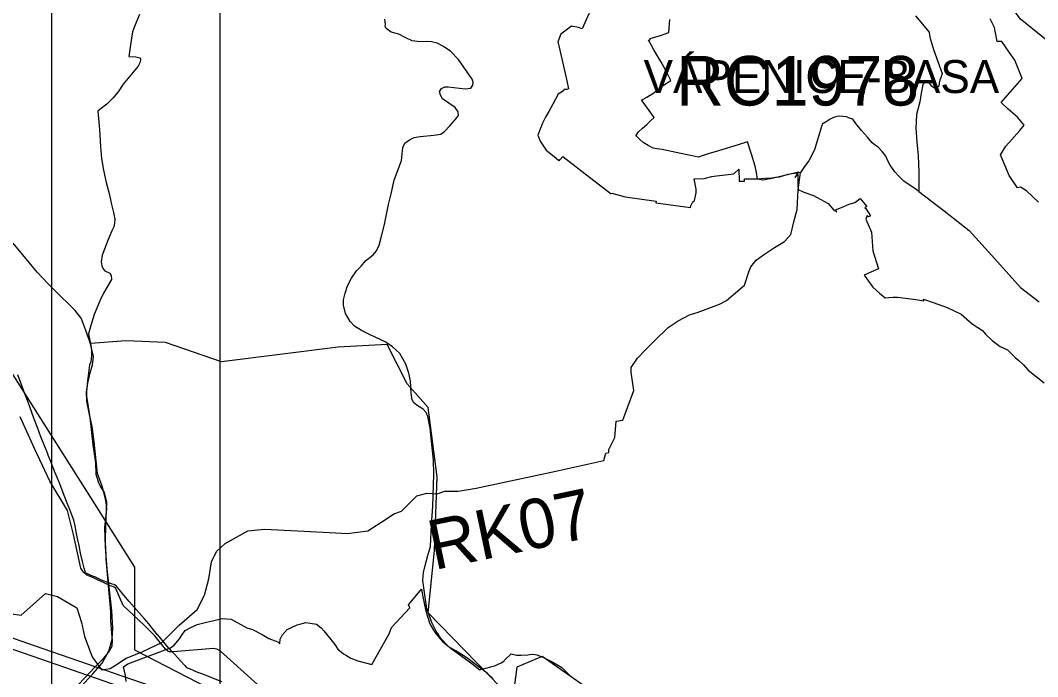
# Model space of a CAD drawing. Extents: x -789162 to -606354, y -1062736 to -945481.
# Drawn here: x -694982 to -691900, y -981501 to -979512 of the extents above; entities that cross this region are included whole.
import ezdxf

# ---------------------------------------------------------------- set-up
doc = ezdxf.new("R2010")
doc.units = 0
for name, color, linetype in [('_Rámeček', 7, 'Continuous'), ('_SIRSI VZTAHY_CYKLOTRASY MISTNI S', 7, 'Continuous'), ('_SIRSI VZTAHY_ELEKTRICKE VEDENI VN 110 kV S', 7, 'Continuous'), ('_SIRSI VZTAHY_ELEKTRICKE VEDENI VN 220 kV S', 7, 'Continuous'), ('_SIRSI VZTAHY_ELEKTRICKE VEDENI VN 400 kV N', 7, 'Continuous'), ('_SIRSI VZTAHY_NATURA_EVL', 7, 'Continuous'), ('_SIRSI VZTAHY_NATURA_EVL_POPIS_KOD', 7, 'Continuous'), ('_SIRSI VZTAHY_PRIRODNIHO PARKU', 7, 'Continuous'), ('_SIRSI VZTAHY_SILNICE III TRIDY_STAV', 7, 'Continuous'), ('_SIRSI VZTAHY_USES_NRBK_S', 7, 'Continuous'), ('_SIRSI VZTAHY_USES_popis S', 7, 'Continuous'), ('_SIRSI VZTAHY_USES_RBC_S', 7, 'Continuous'), ('_SIRSI VZTAHY_USES_RBK_S', 7, 'Continuous'), ('_SIRSI VZTAHY_VTL PLYNOVOD', 7, 'Continuous')]:
    doc.layers.add(name, color=color, linetype=linetype)

msp = doc.modelspace()

# ---------------------------------------------------------------- linework, layer by layer
at = {"layer": '_Rámeček'}
msp.add_lwpolyline([(-673887.2, -995977.3), (-673887.2, -966277.3), (-694887.2, -966277.3), (-694887.2, -995977.3)], close=True, dxfattribs=at)
msp.add_lwpolyline([(-674375.7, -995477.3), (-674375.7, -975976.1), (-694376.9, -975976.1), (-694376.9, -995477.3)], dxfattribs=at)
at = {"layer": '_SIRSI VZTAHY_CYKLOTRASY MISTNI S'}
for points in [[(-691816, -979617.5), (-691951.9, -979508.8), (-692110.7, -979287.6), (-692328, -979211), (-692523.8, -978708.8), (-692486.6, -978493.5), (-692726.7, -977966.7), (-692975.5, -977824), (-693210.7, -977775.4), (-693492.4, -977508.6), (-693619, -977388.9), (-693813.4, -977283.8), (-693821.4, -977198.8), (-693557.4, -977122)], [(-692561.9, -982005.8), (-692792.5, -981838.4), (-692978.4, -981716.2), (-693172.2, -981663), (-693275.7, -981527.5), (-693400.5, -981439.8), (-693477.5, -981471.7), (-693490.8, -981570), (-693745.7, -981307), (-693727.1, -981118.3), (-693719.2, -980895.1), (-693745.7, -980685.2), (-693809.4, -980613.5), (-693870.5, -980493.9), (-694019.2, -980501.9), (-694372.3, -980547.1), (-694542.3, -980488.6), (-694661.8, -980483.3), (-694768, -980491.3)]]:
    msp.add_lwpolyline(points, dxfattribs=at)
at = {"layer": '_SIRSI VZTAHY_ELEKTRICKE VEDENI VN 110 kV S'}
msp.add_lwpolyline([(-695099.9, -981351.1), (-694940.1, -981406.3), (-694671.1, -981499.1), (-694396.2, -981594), (-694167.4, -981672.8), (-693934.1, -981753.4), (-693724.7, -981825.6), (-693504, -981902.1), (-693347.5, -981908.6), (-693148.1, -981916.7), (-692888.5, -981927.1), (-692639.9, -981937.1), (-692439.7, -981945), (-692140.6, -981956.9), (-691924.8, -981965.3), (-691693.6, -981974.7)], dxfattribs=at)
at = {"layer": '_SIRSI VZTAHY_ELEKTRICKE VEDENI VN 220 kV S'}
msp.add_lwpolyline([(-698352.5, -980261.8), (-698011.7, -980379.6), (-697596.3, -980523), (-697419.8, -980584), (-697058, -980709.1), (-696683.3, -980838.6), (-696343.4, -980955.9), (-695974.2, -981083.5), (-695687.1, -981182.6), (-695361.5, -981294.9), (-695116.9, -981379.2), (-694705.9, -981521), (-694311.9, -981656.7), (-693963.7, -981776.7), (-693721.1, -981882.4), (-693400.8, -982021.6), (-693174.7, -982120.1), (-692744.9, -982307.1), (-692311.8, -982495.5), (-691885.3, -982681.2)], dxfattribs=at)
at = {"layer": '_SIRSI VZTAHY_ELEKTRICKE VEDENI VN 400 kV N'}
msp.add_lwpolyline([(-695022, -980558.7), (-694898.3, -980754), (-694781.6, -980938.6), (-694636.2, -981168.6), (-694635.8, -981419), (-694349.9, -981567.1), (-694229.6, -981729.7), (-693978.3, -981813.9), (-693730.2, -981922.8), (-693442.6, -982049), (-693232.3, -982141.5), (-692774.3, -982341.3), (-692334, -982533.2), (-692003.5, -982678), (-691832.7, -982796.8)], dxfattribs=at)
at = {"layer": '_SIRSI VZTAHY_NATURA_EVL'}
for points in [[(-693237.9, -979444), (-693279.9, -979537.8), (-693290.4, -979533.3), (-693311.8, -979529.6), (-693343.8, -979553.9), (-693353.5, -979577), (-693350.2, -979589.4), (-693340.9, -979628.3), (-693326.1, -979695.8), (-693321.5, -979719.4), (-693326, -979721.4), (-693329.1, -979721.3), (-693334.9, -979721.2), (-693336.4, -979725.2), (-693352.2, -979735.8), (-693368.7, -979766.3), (-693381.1, -979788.4), (-693389.5, -979803.6), (-693400.2, -979823.2), (-693414, -979860.1), (-693406.4, -979878.3), (-693388.9, -979905.6), (-693383.8, -979909.9), (-693364.9, -979925.1), (-693351.8, -979935.8), (-693349.4, -979937.9), (-693346.3, -979934), (-693338.1, -979924.8), (-693279.7, -979969.8), (-693191.9, -980037.4), (-693189.5, -980035.5), (-693149.2, -980047.2), (-693055.9, -980060.1), (-693056.4, -980065.1), (-692951.4, -980079.2), (-692950.4, -980074.1), (-692943.9, -980062.2), (-692939.4, -980057.7), (-692934.1, -980035.1), (-692934.7, -980024), (-692940.6, -979992.3), (-692910.4, -979991.1), (-692886.9, -979985.6), (-692872.2, -979983.6), (-692819.9, -979977.2), (-692804.7, -979963.3), (-692804.4, -979999.8), (-692787.8, -979999.8), (-692787.8, -979992.3), (-692749.2, -979991.9), (-692732.7, -979995.5), (-692725, -979994.1), (-692712, -979990.9), (-692707.7, -979990.9), (-692682.8, -979985.7), (-692623.8, -979970.6), (-692635.3, -979988.6), (-692626.2, -979978.8), (-692626.6, -979987.5), (-692626.4, -979999), (-692626.7, -980016.6), (-692625.2, -980020.8), (-692625, -980024.8), (-692607.6, -980033), (-692578.5, -980043.1), (-692534.2, -980067), (-692516.7, -980087.6), (-692511.3, -980090), (-692507.7, -980093.6), (-692512.1, -980085.9), (-692494.3, -980078.8), (-692471.1, -980069.2), (-692453.7, -980064.5), (-692437, -980051.5), (-692416.7, -980075.9), (-692422.9, -980079.8), (-692420.5, -980082.5), (-692406, -980104.3), (-692412, -980107.2), (-692416, -980103.5), (-692420.5, -980114.5), (-692403.1, -980153.6), (-692399.5, -980210.2), (-692382.2, -980264.9), (-692395.9, -980270.9), (-692425.2, -980283.7), (-692398.7, -980320.3), (-692379.2, -980339.1), (-692361.2, -980352.6), (-692350.3, -980352), (-692337.9, -980351.3), (-692324.3, -980350.9), (-692269.1, -980357.4), (-692244.9, -980361.9), (-692245.1, -980356.6), (-692215.9, -980367.2), (-692173.4, -980382.2), (-692130.9, -980402.1), (-692098.5, -980431.5), (-692067.1, -980451.9), (-692057.2, -980463.3), (-692037.7, -980482.4), (-692013.7, -980500.1), (-691991.2, -980510.4), (-691967.3, -980533.6), (-691957.1, -980543.2), (-691942.6, -980556.2), (-691928.1, -980572.4), (-691903.9, -980590.9), (-691880.3, -980609.9)], [(-691897.5, -980062.5), (-691933.1, -980028.5), (-691951.6, -980017.7), (-691960.9, -980019.2), (-691986.1, -979982.2), (-692012.2, -979919.1), (-691996.3, -979893.1), (-691953.5, -979846), (-691940.3, -979830), (-691960.5, -979805.2), (-691988.9, -979780.7), (-692010.5, -979760.8), (-691946.7, -979688.6), (-691969.3, -979632.6), (-691985.8, -979608.6), (-692008.6, -979576.5), (-692022.4, -979575.8), (-692027.7, -979549.6), (-692030.2, -979534.1), (-692043.8, -979507.1)]]:
    msp.add_lwpolyline(points, dxfattribs=at)
at = {"layer": '_SIRSI VZTAHY_PRIRODNIHO PARKU'}
for points in [[(-694621, -979494.7), (-694634, -979525.2), (-694642, -979547.3), (-694648, -979586.2), (-694653, -979621.4), (-694632, -979622.4), (-694620, -979625.2), (-694618, -979628.9), (-694619, -979638.8), (-694625, -979650.5), (-694670, -979705.8), (-694685, -979728.8), (-694702, -979748.1), (-694720, -979766.4), (-694741, -979782.4), (-694747, -979787.5), (-694742, -979842.4), (-694739, -979894.5), (-694736, -979930.6), (-694730, -979965.9), (-694722, -980003.4), (-694713, -980037.2), (-694706, -980070), (-694700, -980094.5), (-694695, -980114.6), (-694696, -980126.4), (-694699, -980137.3), (-694705, -980149.5), (-694718, -980181.4), (-694725, -980200.2), (-694734, -980223.8), (-694737, -980243.9), (-694735, -980255.7), (-694731, -980264.5), (-694726, -980271.4), (-694711, -980278.2), (-694707, -980284.9), (-694706, -980297.5), (-694730, -980338.6), (-694740, -980359.5), (-694758, -980403.2), (-694765, -980426.1), (-694770, -980443.9), (-694775, -980461.6), (-694769, -980492.3), (-694768, -980496.7), (-694766, -980513.6), (-694766, -980528.7), (-694768, -980546.7), (-694772, -980555.7), (-694778, -980604.6), (-694781, -980637), (-694781, -980643.5), (-694781, -980650.5), (-694771, -980715.3), (-694762, -980798), (-694754, -980853.2), (-694753, -980886.7), (-694749, -980899.5), (-694746, -980909.9), (-694739, -980925.2), (-694728, -980943), (-694724, -980958.6), (-694721, -980971.4), (-694722, -980999.6), (-694724, -981042), (-694725, -981089.8), (-694724, -981117.2), (-694723, -981126.7), (-694723, -981143.4), (-694716, -981225.2), (-694709, -981303.6), (-694709, -981320.7), (-694708.3, -981331.9), (-694706, -981368.5), (-694704, -981391.2), (-694705, -981408.9), (-694713, -981423.1), (-694734, -981449.2), (-694756, -981472), (-694805, -981523)], [(-694661, -981515.7), (-694663, -981497.4), (-694669, -981470.6), (-694656, -981462.1), (-694527, -981413.8), (-694516, -981404.8), (-694500, -981385.6), (-694490, -981372.2), (-694482, -981360.8), (-694465, -981352.2), (-694446, -981343.1), (-694418, -981335.5), (-694400, -981331.7), (-694370, -981324.3), (-694343, -981326.9), (-694296, -981353), (-694278, -981357.9), (-694249.4, -981372.8), (-694229.2, -981384.7), (-694202, -981395.1), (-694195.1, -981401.3), (-694195, -981386.9), (-694189, -981375.1), (-694173, -981358), (-694143, -981343.7), (-694135, -981341.6), (-694117, -981336.9), (-694084, -981342), (-694070, -981353), (-694062, -981361.4), (-694029, -981403.5), (-694020, -981416.9), (-694003, -981431.3), (-693994, -981436.5), (-693980, -981444.8), (-693959, -981452.7), (-693917, -981463.6), (-693864, -981371.3), (-693857, -981352.1), (-693802, -981292.4), (-693806, -981282.8), (-693766, -981235.3), (-693762, -981259), (-693754, -981296.7), (-693749, -981315.7), (-693741, -981340.8), (-693730, -981359.7), (-693724, -981369.3), (-693711, -981385.1), (-693702, -981394.9), (-693677, -981415.8), (-693614, -981460.4), (-693590, -981479.7), (-693582, -981477.1), (-693571, -981474.7), (-693556, -981471), (-693542, -981466.9), (-693534, -981463), (-693525, -981458.3), (-693520, -981456), (-693516, -981452.3), (-693515, -981450.2), (-693495, -981431.8), (-693483, -981434.3), (-693479, -981435.6), (-693471, -981435.8), (-693464, -981435.8), (-693444, -981434.2), (-693438, -981433.1), (-693430, -981432.9), (-693422, -981433.7), (-693417, -981435), (-693399, -981441.7), (-693381, -981450.4), (-693369, -981456.3), (-693356, -981463.4), (-693341, -981472.5), (-693313, -981501.7)]]:
    msp.add_lwpolyline(points, dxfattribs=at)
at = {"layer": '_SIRSI VZTAHY_SILNICE III TRIDY_STAV'}
for points in [[(-693549.1, -981507.1), (-693567.9, -981490), (-693629.1, -981443.6), (-693662.5, -981422.4), (-693683.7, -981410.7), (-693707.2, -981386.2), (-693722.4, -981363.2), (-693734.9, -981336.1), (-693750.1, -981294.7), (-693757.1, -981245.2), (-693762.2, -981209), (-693760.3, -981185.2), (-693755.2, -981164.2), (-693746.9, -981133.8), (-693739, -981106.1), (-693736.6, -981039.6), (-693732, -980985.2), (-693728.8, -980887.2), (-693729.8, -980845.1), (-693734.6, -980797.6), (-693740.5, -980747.7), (-693746.9, -980712), (-693752.7, -980700.3), (-693761.6, -980690.5), (-693776.5, -980680.7), (-693789.2, -980670.8), (-693794.9, -980661.9), (-693797.8, -980642.1), (-693799.3, -980604.6), (-693804.8, -980580.7), (-693813.9, -980554), (-693832.1, -980521.8), (-693854.6, -980501.6), (-693876.9, -980486.1), (-693921.7, -980464.9), (-693948.6, -980451.8), (-693969.1, -980438.9), (-693983, -980424.8), (-693996.3, -980399.9), (-694002.8, -980375.2), (-694002.3, -980359.2), (-693997.9, -980338.7), (-693990.5, -980316.8), (-693978, -980292.9), (-693963.7, -980271.3), (-693949.4, -980256.5), (-693936.2, -980240.6), (-693913, -980222.8), (-693902.9, -980210.6), (-693894.4, -980192.8), (-693887.9, -980166.3), (-693878.5, -980130.2), (-693866.3, -980069.9), (-693858.6, -980038.1), (-693849.4, -979996.2), (-693826.9, -979936.5), (-693825, -979917.7), (-693822.8, -979897.7), (-693816.4, -979884.1), (-693802.7, -979874.4), (-693788.2, -979866.6), (-693770.7, -979863.6), (-693728.9, -979860.2), (-693707.6, -979856.8), (-693696.9, -979849), (-693680.6, -979831.7), (-693666, -979815.8), (-693654.8, -979800.6), (-693654.9, -979789.5), (-693664.7, -979776.4), (-693702.8, -979749.8), (-693708.8, -979739), (-693711.4, -979727.5), (-693706, -979718.7), (-693695.5, -979713.6), (-693685.1, -979713.4), (-693634.2, -979719.6), (-693617.4, -979717.7), (-693610.4, -979708.2), (-693610.1, -979699.3), (-693613.3, -979690.7), (-693654.8, -979630.5), (-693677.1, -979606.9), (-693699.9, -979591.7), (-693719.3, -979581.5), (-693736.1, -979577), (-693750.3, -979576.3), (-693770.8, -979577), (-693794.2, -979574.2), (-693815.7, -979564.5), (-693834.6, -979553.9), (-693858.1, -979547.5), (-693873, -979536.4), (-693876.5, -979530.1), (-693875.8, -979523.7), (-693877.8, -979508.6)], [(-694837.9, -981574.1), (-694762.3, -981492.6), (-694734, -981459.9), (-694722.3, -981439.6), (-694712.4, -981420.3), (-694703.3, -981386.8), (-694701.7, -981353.3), (-694704.6, -981301.4), (-694718.8, -981173.8), (-694723.5, -981106.9), (-694725.8, -981048.8), (-694719.7, -980992.6), (-694721.3, -980972.6), (-694725.1, -980957.4), (-694733.7, -980923.9), (-694747.6, -980885.2), (-694758.1, -980788.8), (-694764, -980742.5), (-694772, -980706.8), (-694780.5, -980666.4), (-694781.7, -980638.6), (-694777.3, -980611.6), (-694769.9, -980580.4), (-694762.9, -980556.3), (-694760.2, -980531), (-694764.1, -980513.8), (-694770.5, -980489.3), (-694778.9, -980463.1), (-694790, -980432.3), (-694797.8, -980414.7), (-694815.8, -980391.7), (-694834.9, -980372.2), (-694859.8, -980348), (-694898.8, -980309.9), (-694931, -980274.8), (-695003.4, -980187)]]:
    msp.add_lwpolyline(points, dxfattribs=at)
at = {"layer": '_SIRSI VZTAHY_USES_NRBK_S'}
msp.add_lwpolyline([(-692259.4, -980030.8), (-692183.2, -980089.7), (-692106.9, -980148.5), (-692029.2, -980235.1), (-691951.4, -980321.6), (-691895.1, -980364.5)], dxfattribs=at)
at = {"layer": '_SIRSI VZTAHY_USES_RBC_S'}
msp.add_lwpolyline([(-692270, -979498), (-692228.3, -979548.1), (-692227, -979557), (-692225.3, -979566.6), (-692220.3, -979583.7), (-692215.2, -979600.8), (-692201.9, -979637.2), (-692188.6, -979673.6), (-692192.2, -979683.3), (-692195.9, -979693.1), (-692197.6, -979702.3), (-692199.3, -979711.6), (-692203.9, -979715.8), (-692208.5, -979719.9), (-692213.9, -979716.2), (-692219.4, -979712.4), (-692225.2, -979705.7), (-692231.1, -979699), (-692240.3, -979699), (-692247.8, -979706.5), (-692252.4, -979732.9), (-692257, -979759.2), (-692262, -979778.5), (-692267.1, -979797.8), (-692267.9, -979818.2), (-692268.8, -979838.7), (-692265.4, -979880.5), (-692262.1, -979922.4), (-692260.8, -979947.3), (-692259.4, -979972.2), (-692259.4, -980001.5), (-692259.4, -980030.8), (-692272, -980021.6), (-692288.8, -980010.3), (-692305.5, -979999), (-692318.9, -979985.2), (-692332.3, -979971.3), (-692339.4, -979961.3), (-692346.6, -979951.2), (-692353.2, -979937.4), (-692359.8, -979923.6), (-692371.2, -979909.8), (-692382.6, -979896), (-692391.8, -979889.8), (-692400.9, -979883.6), (-692415.6, -979866.2), (-692432.9, -979845.4), (-692450.2, -979824.6), (-692460.1, -979812), (-692469.6, -979808.1), (-692479.1, -979804.2), (-692489.9, -979803.4), (-692500.7, -979802.5), (-692508.1, -979803.8), (-692515.4, -979805.1), (-692521.9, -979808.6), (-692528.4, -979812), (-692540.6, -979819.5), (-692552.8, -979827.1), (-692553.8, -979830.4), (-692564.7, -979867.3), (-692575.6, -979904.2), (-692593.3, -979937.5), (-692605.8, -979955.2), (-692618.4, -979973), (-692630.1, -979974.7), (-692649.1, -979977.8), (-692656.5, -979979.1), (-692669.7, -979983), (-692682.8, -979987), (-692694, -979988.6), (-692705.1, -979990.1), (-692726.7, -979991.4), (-692748.2, -979992.8), (-692751.6, -979973.5), (-692755, -979954.3), (-692766.7, -979917.4), (-692778.3, -979880.6), (-692807.2, -979889.3), (-692866.7, -979907.4), (-692897.5, -979917), (-692928.3, -979926.6), (-692945.9, -979923), (-692966.7, -979918.8), (-692980.9, -979915.6), (-693009.2, -979909.4), (-693037.4, -979903.1), (-693053, -979901.2), (-693064.1, -979899.8), (-693079.7, -979891.2), (-693095.2, -979882.5), (-693104.7, -979873.2), (-693114.2, -979863.9), (-693116.6, -979861.6), (-693113.3, -979856.4), (-693109.8, -979850.8), (-693096.8, -979839), (-693083.8, -979827.2), (-693072.5, -979817), (-693061.2, -979806.8), (-693066.4, -979799.6), (-693082.1, -979777.8), (-693097.8, -979756), (-693099.4, -979753.9), (-693083.9, -979744.5), (-693062.1, -979731.3), (-693036.7, -979710.5), (-693011, -979694.5), (-693026.4, -979663.6), (-693041.2, -979636.8), (-693062.1, -979601.1), (-693070.5, -979586.6), (-693078.9, -979572.1), (-693072.3, -979569.9), (-693073.5, -979567.4), (-693042.5, -979557.5), (-693017.4, -979548.8), (-693014, -979509.9)], dxfattribs=at)
at = {"layer": '_SIRSI VZTAHY_USES_RBK_S'}
msp.add_lwpolyline([(-695037.8, -981305.9), (-694979.6, -981314.5), (-694942.8, -981281.9), (-694905.9, -981249.2), (-694869.6, -981257.4), (-694810.2, -981292.1), (-694796.2, -981336.8), (-694787.6, -981379.1), (-694764.5, -981441.1), (-694735.8, -981480), (-694709.2, -981475.9), (-694693.9, -981465.8), (-694661.4, -981444.3), (-694612.9, -981425.1), (-694553.4, -981396.9), (-694500.9, -981344.4), (-694446, -981296.7), (-694423.9, -981254), (-694410.9, -981204.7), (-694403.1, -981152.7), (-694387.7, -981121.8), (-694361.1, -981097.4), (-694292.5, -981058.7), (-694241.7, -981053.4), (-694142, -981058.8), (-694026, -981065.1), (-693991.5, -981067), (-693928.8, -981058.6), (-693875.7, -981024.3), (-693850, -981007.6), (-693827.1, -980999.5), (-693798, -980970.4), (-693780.5, -980952.9), (-693750.1, -980944.7), (-693718.8, -980946.4), (-693695.4, -980938.3), (-693670.6, -980938.8), (-693655.8, -980939.1), (-693600.7, -980929.4), (-693359.3, -980877.6), (-693214.4, -980845.9), (-693207.6, -980823.1), (-693198.7, -980821.1), (-693199, -980811.9), (-693181.1, -980775.6), (-693176.8, -980726.8), (-693156.1, -980723.4), (-693122.6, -980633.5), (-693131.1, -980577.7), (-693131.1, -980563.6), (-693112.1, -980535.9), (-693088.3, -980511.5), (-693059.5, -980482), (-693018.8, -980442.7), (-692988.4, -980422.9), (-692954.4, -980404.8), (-692928.4, -980396.4), (-692895.9, -980384.1), (-692863.4, -980371.7), (-692842.6, -980360.5), (-692815.3, -980337.6), (-692787.9, -980314.6), (-692774.3, -980273.6), (-692768.8, -980258.9), (-692752.1, -980238.3), (-692730.7, -980222.1), (-692696.6, -980200.7), (-692666.6, -980182.3), (-692647.8, -980160.8), (-692638, -980122.9), (-692628.2, -980085), (-692625.3, -980026), (-692618.4, -979973)], dxfattribs=at)
at = {"layer": '_SIRSI VZTAHY_VTL PLYNOVOD'}
for points in [[(-694521.4, -981425.3), (-694527.8, -981418.2), (-694530.7, -981414.9), (-694537.7, -981407), (-694547.1, -981396.2), (-694565.6, -981374.4), (-694566, -981374), (-694566.3, -981373.6), (-694582.3, -981353.6), (-694592.8, -981340.5), (-694607.1, -981324.4), (-694621.7, -981307.5), (-694636.7, -981290.4), (-694652.4, -981272.5), (-694668, -981254), (-694686.1, -981231.2), (-694691.7, -981225), (-694696.4, -981222.6), (-694697.5, -981222), (-694698.3, -981221.7), (-694703.4, -981220.1), (-694710.3, -981217.8), (-694716.6, -981215.6), (-694724.6, -981212.7), (-694735.4, -981208), (-694752.1, -981200.6), (-694756.3, -981198.5), (-694759.7, -981197), (-694760.4, -981196.7), (-694775.8, -981189.9), (-694782, -981186.8), (-694784.2, -981184.6), (-694785.7, -981182.3), (-694788.7, -981172), (-694793.2, -981152.1), (-694799, -981126.4), (-694804, -981103.4), (-694808.5, -981081.7), (-694813.2, -981057.3), (-694815, -981047.7), (-694815.6, -981045.2), (-694815.9, -981043.7), (-694819.7, -981026.5), (-694830.6, -980997.5), (-694841.5, -980969.9), (-694851.8, -980943.5), (-694862.4, -980916.5), (-694875.8, -980883), (-694886.9, -980855.3), (-694889.7, -980848.3), (-694898, -980827.8), (-694898.5, -980826.7), (-694898.9, -980825.4), (-694907.6, -980803.6), (-694919.6, -980773.6), (-694929.8, -980745.5), (-694940.4, -980717.6), (-694952.9, -980683.4), (-694960.2, -980663.7), (-694964.8, -980651.3), (-694976.4, -980621.3), (-694989.2, -980586.5)], [(-694521.4, -981425.3), (-694527.9, -981426.3), (-694535.1, -981423.6), (-694542.2, -981417.5), (-694574.8, -981376.9), (-694598.7, -981352.5), (-694598.9, -981352.3), (-694604.9, -981346.2), (-694622.5, -981329.8), (-694670.2, -981285.5), (-694693.9, -981231.4), (-694699.7, -981228.7), (-694706.5, -981226.1), (-694727.3, -981216.2), (-694747.8, -981207.2), (-694758.1, -981202.7), (-694777.6, -981193.7), (-694781.2, -981192), (-694790.6, -981184.2), (-694798.3, -981171.8), (-694820.5, -981070.3), (-694838.8, -980997.1), (-694892.3, -980908.6), (-694914.3, -980861.2), (-694938.4, -980809.6), (-694982.6, -980713.1)], [(-693668.6, -981791.9), (-693668.7, -981791.6), (-693670.8, -981782.8), (-693673.2, -981775.9), (-693681.1, -981769.5), (-693817.3, -981717.2), (-693938.8, -981669.9), (-694084.9, -981617.1), (-694121.6, -981608.4), (-694132.4, -981605.9), (-694200.7, -981571.8), (-694231.3, -981553.6), (-694241, -981549.2), (-694263.1, -981524.4), (-694375.2, -981423.2), (-694386.6, -981417.3), (-694396.5, -981415.4), (-694518.8, -981425.1), (-694520.4, -981425.2), (-694521.4, -981425.3), (-694521.4, -981425.3)], [(-694521.4, -981425.3), (-694513.4, -981434), (-694496.2, -981452.9), (-694483.7, -981466.8), (-694478.1, -981472.5), (-694476.2, -981473.6), (-694473.6, -981474.8), (-694467.4, -981477.3), (-694458.5, -981481.1), (-694457.3, -981481.6), (-694456.1, -981482.1), (-694452.1, -981483.7), (-694444.6, -981487.1), (-694429.8, -981492.2), (-694372, -981515.4)]]:
    msp.add_lwpolyline(points, dxfattribs=at)

# ---------------------------------------------------------------- texts
at = {"layer": '_SIRSI VZTAHY_NATURA_EVL_POPIS_KOD'}
msp.add_text('VÁPENICE-BASA', height=100, dxfattribs=at).set_placement((-693093.6, -979732.4))
at = {"layer": '_SIRSI VZTAHY_USES_popis S'}
msp.add_text('RC1978', height=150, dxfattribs=at).set_placement((-692994.9, -979770.1))
msp.add_text('RK07', height=150, rotation=11.8502, dxfattribs=at).set_placement((-693728.3, -981178.1))

doc.saveas('drawing.dxf')
